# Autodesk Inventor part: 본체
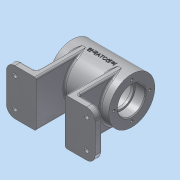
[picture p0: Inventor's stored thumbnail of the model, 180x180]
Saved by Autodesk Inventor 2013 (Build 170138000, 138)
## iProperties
Created: 2017-02
Part Number: 본체
Material: 알루미늄 6061
Document SubType Name: Modeling
Designer: dgall
Density: 2.71 g/cm^3
Mass: 356.083 g
Surface Area: 422.768 cm^2
Volume: 131.396 cm^3
Author: dgall
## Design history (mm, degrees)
sketch "스케치1"
  geometry: L1 (0, 0)-(70, 0); L2 (0, 16)-(11.7, 16); L3 (12, 15.7)-(12, 14); L4 (12, 14)-(15, 14); L5 (15, 14)-(15, 19); L6 (18, 22)-(52, 22); L7 (55, 19)-(55, 14); L8 (55, 14)-(58, 14); L9 (58, 14)-(58, 15.7); L10 (58.3, 16)-(70, 16); L11 (0, 16)-(0, 27); L12 (0, 27)-(70, 27); L13 (70, 27)-(70, 16); A1 r 0.3 centre (11.7, 15.7) between (12, 15.7) and (11.7, 16); A2 r 0.3 centre (58.3, 15.7) between (58.3, 16) and (58, 15.7); A3 r 3 centre (52, 19) between (55, 19) and (52, 22); A4 r 3 centre (18, 19) between (18, 22) and (15, 19); 4 further points
  constraints: 26 end point, 8 parallel, 8 point on circle, 8 point on line, 8 tangent, 4 centre point, 3 perpendicular, 2 equal radius, 2 vertical alignment, 1 collinear, 1 horizontal
  dimensions: "d0" = 70 distance of L1.start L1.end; "d4" = 28 diameter of L8 L1; "d5" = 32 diameter of L10 L1; "d6" = 12 distance of point (58, 16) L10.end; "d7" = 12 distance of L2.start point (12, 16); "d8" = 32 diameter of L2 L1; "d9" = 28 diameter of L4 L1; "d10" = 40 distance of point (15, 22) point (55, 22); "d11" = 44 diameter of L6 L1; "d12" = 3 distance of L3.end L4.end; "d13" = 54 diameter of L12 L1; "d14" = 0.3 radius of A1; "d15" = 3 radius of A3
revolve "회전1" sketch "스케치1" stored, may be unused: angle "d16" = 90 deg
sketch "스케치2" dims "d17" = 42
  geometry: C1 r 16 at (0, 0) reference; C2 r 27 at (0, 0) reference; 2 further points
  constraints: 2 vertical alignment, 1 coincident, 2 other
hole "구멍1" sketch "스케치2" at (0, 21) diameter "d19" = 3.242; stored, may be unused: countersink angle "d23" = 90 deg, drill point angle "d25" = 118 deg; dims "d20" = 8, "d21" = 4, "d22" = 2, "d24" = 10
sketch "스케치3" dims "d29" = 42
  geometry: C1 r 27 at (0, 0) reference; C2 r 16 at (0, 0) reference; 2 further points
  constraints: 2 vertical alignment, 1 coincident, 2 other
hole "구멍2" sketch "스케치3" at (0, 21) diameter "d31" = 3.242; stored, may be unused: countersink angle "d35" = 90 deg, drill point angle "d37" = 118 deg; dims "d32" = 8, "d33" = 4, "d34" = 2, "d36" = 10
node "작업 평면1"
sketch "스케치4"
  geometry: L1 (0, 27)-(0, -27) reference; L2 (-87, 27)-(17, 27); L3 (-87, 27)-(-87, -27); L4 (-87, -27)-(17, -27); L5 (17, -27)-(17, 27); L6 (0, 27)-(-70, 27) reference; 5 further points
  constraints: 8 end point, 4 midpoint, 3 perpendicular, 1 horizontal alignment, 1 parallel, 1 vertical alignment
  dimensions: "d42" = 104 distance of L2.start L2.end; "d44" = 54 distance of L2.start L3.end
extrude "돌출1" join sketch "스케치4" distance "d45" = 8; taper "d46" = 0 deg
sketch "스케치5"
  geometry: L1 (-17, -27)-(87, -27) reference; L2 (87, 27)-(-17, 27) reference; L3 (35, 27)-(35, -27); L4 (18, 27)-(18, -27); L5 (52, 27)-(52, -27); 1 further point
  constraints: 6 end point, 4 point on line, 2 midpoint, 1 parallel, 1 perpendicular
  dimensions: "d47" = 17 distance between parallel lines of L3 L4; "d48" = 17 distance between parallel lines of L5 L3
extrude "돌출2" cut sketch "스케치5" stored distance "d49" = 8; taper "d50" = 0 deg
fillet "모깎기1" dims "d51" = 10
sketch "스케치6" dims "d52" = 9
  geometry: L1 (79.598, 21.5)-(82.196, 17); L2 (82.196, 17)-(79.598, 12.5); L3 (79.598, 12.5)-(74.402, 12.5); L4 (74.402, 12.5)-(71.804, 17); L5 (71.804, 17)-(74.402, 21.5); L6 (74.402, 21.5)-(79.598, 21.5); A1 r 10 centre (77, 17) between (87, 17) and (77, 27) reference; 4 further points
  constraints: 12 end point, 2 coincident, 2 vertical alignment, 1 midpoint, 15 other
extrude "돌출3" cut sketch "스케치6" distance "d54" = 3; taper "d55" = 0 deg
hole "구멍3" diameter "d58" = 5; stored, may be unused: countersink angle "d62" = 90 deg, drill point angle "d64" = 118 deg; dims "d56" = 10, "d57" = 10, "d59" = 8, "d60" = 4, "d61" = 2, "d63" = 10
sketch "스케치7"
  geometry: L1 (77, 27)-(52, 27) reference; L2 (52, 27)-(52, -27) reference; L3 (52, -27)-(77, -27) reference; L4 (60, 27)-(60, -27); 1 further point
  constraints: 2 end point, 2 point on line, 1 perpendicular
  dimensions: "d71" = 8 distance between parallel lines of L4 L2
extrude "돌출4" join sketch "스케치7" stored distance "d72" = 3; taper "d73" = 0 deg
sketch "스케치8"
  geometry: L1 (-7, -27)-(18, -27) reference; L2 (18, -27)-(18, 27) reference; L3 (18, 27)-(-7, 27) reference; L4 (10, 27)-(10, -27); 1 further point
  constraints: 2 end point, 2 point on line, 1 perpendicular
  dimensions: "d74" = 8 distance between parallel lines of L4 L2
extrude "돌출5" join sketch "스케치8" stored distance "d75" = 3; taper "d76" = 0 deg
fillet "모깎기2" dims "d77" = 2
node "작업 평면2"
sketch "스케치9"
  geometry: C1 r 5 at (-25, 0); 1 further point
  constraints: 1 centre point, 1 horizontal alignment
  dimensions: "d79" = 10 diameter of C1; "d81" = 25 distance of point (0, 0) C1.centre
extrude "돌출6" join sketch "스케치9" stored distance "d82" = 3; taper "d83" = 0 deg
hole "구멍4" diameter "d86" = 5.188; stored, may be unused: countersink angle "d90" = 90 deg, drill point angle "d92" = 118 deg; dims "d84" = 10, "d85" = 10, "d87" = 20, "d88" = 4, "d89" = 2, "d91" = 10
fillet "모깎기3" dims "d93" = 2
node "작업 평면3"
sketch "스케치10"
  geometry: L1 (0, 0)-(16.339, -25.16); L2 (0, 0)-(0, -27); A1 r 27 centre (0, 0) between (-23.276, -13.683) and (23.276, -13.683) reference
  constraints: 4 end point, 1 point on circle
  dimensions: "d95" = 33 deg angle of L1 L2; "d96" = 30 distance of L1.start L1.end
node "작업 평면4"
sketch "스케치11"
  geometry: C1 r 6 at (0, 0); 1 further point
  constraints: 1 centre point, 1 horizontal alignment
  dimensions: "d97" = 12 diameter of C1; "d99" = 35 distance of C1.centre point (-35, 0)
extrude "돌출7" join sketch "스케치11" stored distance "d100" = 3; taper "d101" = 0 deg
fillet "모깎기4" dims "d102" = 2
hole "구멍5" diameter "d105" = 5.188; stored, may be unused: countersink angle "d109" = 90 deg, drill point angle "d111" = 118 deg; dims "d103" = 10, "d104" = 10, "d106" = 20, "d107" = 4, "d108" = 2, "d110" = 10
chamfer "모따기1" distance "d112" = 1; stored, may be unused: second distance "d113" = 2, angle "d114" = 45 deg
node "작업 평면5"
sketch "스케치12"
  geometry: L1 (0, 27)-(70, 27) reference; 2 further points
  constraints: 1 other
  dimensions: "d116" = 35 distance of point (35, 0) point (0, 0); "d117" = 27 distance from line of point (35, 0) L1
feature "엠보싱1" sketch "스케치12" dims "d118" = 0.5, "d119" = 0
node "솔리드1"
pattern_circular "원형 패턴1" dims angle "d27" = 360 deg
pattern_circular "원형 패턴2" dims angle "d39" = 360 deg
pattern_linear "직사각형 패턴1" dims "d67" = 34
pattern_linear "직사각형 패턴2" dims "d70" = 84
other parameters: "d78" = 32, "d94" = -35
